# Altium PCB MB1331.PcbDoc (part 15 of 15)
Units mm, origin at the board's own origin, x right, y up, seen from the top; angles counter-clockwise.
Board outline 169.25 x 173.25 mm, 6 copper layers (Top Layer, Signal Layer 1, Signal Layer 2, Signal Layer 3, Signal Layer 4, Bottom Layer), stack 1.556 mm thick; 871 components, 699 nets, 3244 pads, 2370 vias.
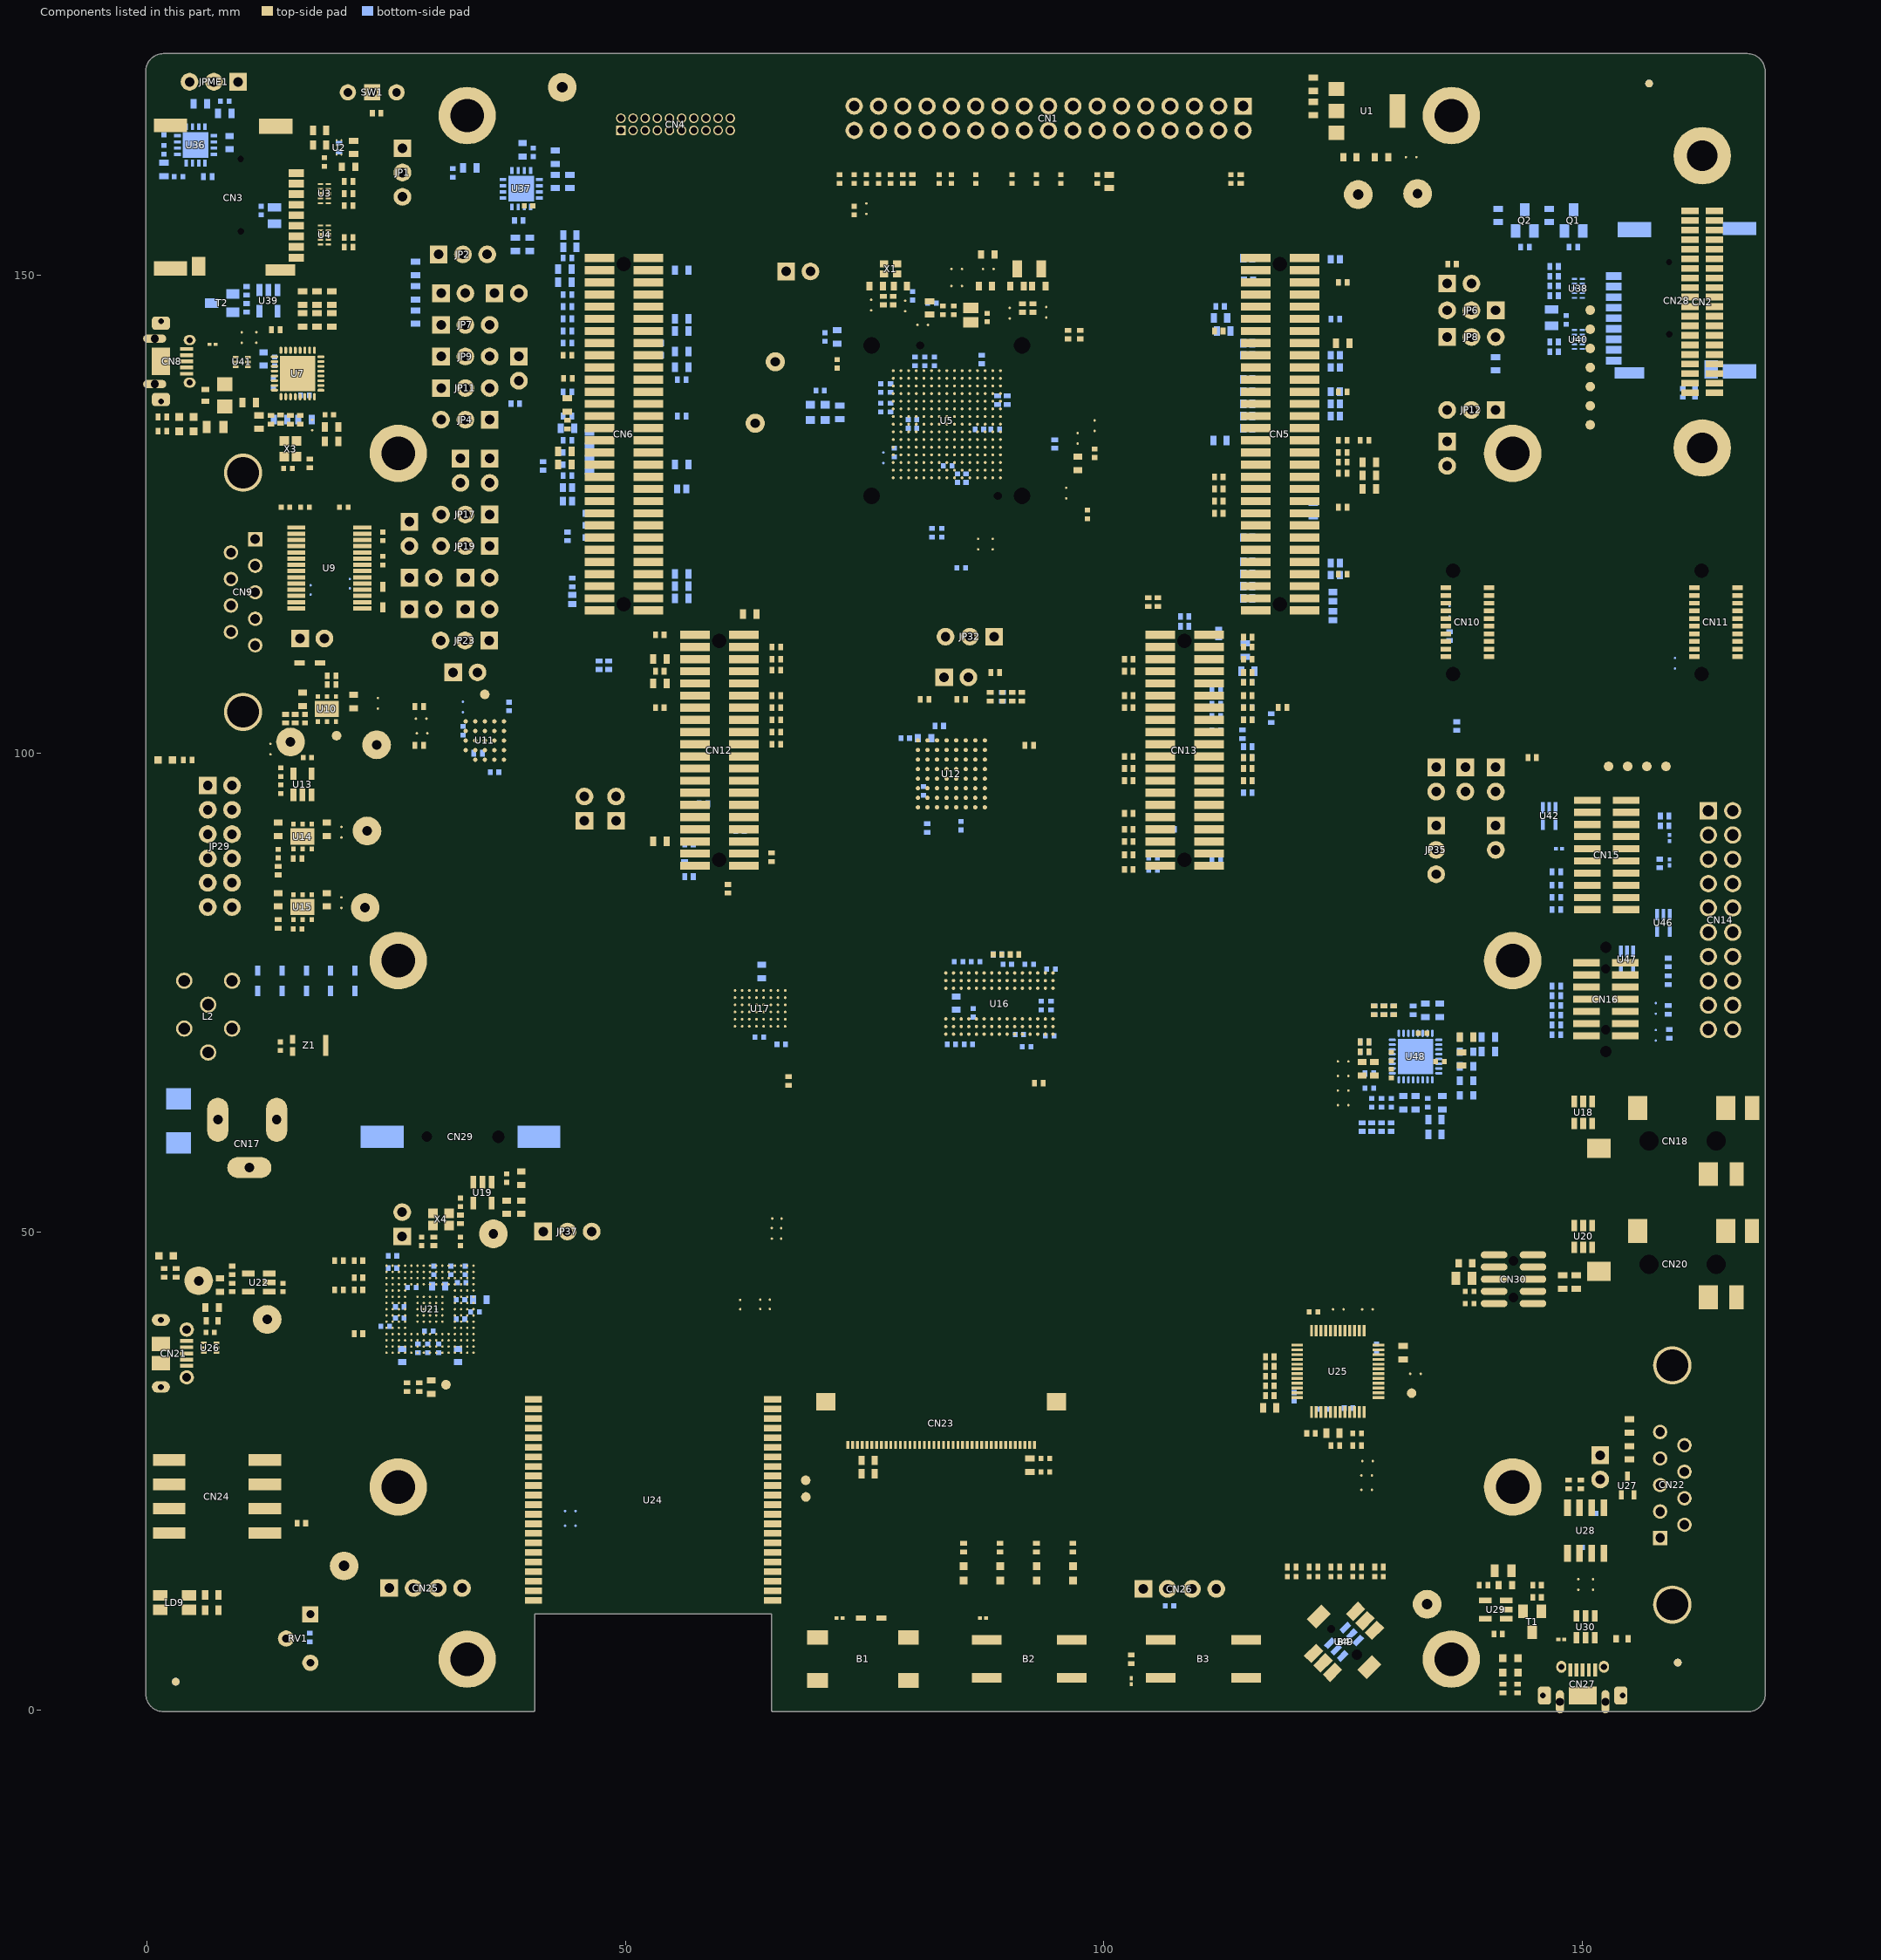
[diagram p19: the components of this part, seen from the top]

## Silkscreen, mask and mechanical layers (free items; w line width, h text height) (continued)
Drill Drawing:
  drawing of 559 lines, arcs and shapes, not listed
  text "Layer" at 186.981,220.375 h3
  text "Name" at 199.538,220.375 h3
  text "Material" at 223.825,220.375 h3
  text "Thickness" at 248.245,220.375 h3
  text "Constant" at 266.172,220.375 h3
  text "Board Layer Stack" at 282.763,220.375 h3
  text "PCB SPECIFICATIONS :" at -5.634,219.549 h3
  text "**Plating type :" at 111.416,219.199 h2.5
  text "PCB : TYPE 3" at 145.373,218.081 h3
  text "A.   MATERIAL :" at -5.634,215.549 h3
  text "FR-4" at 32.866,215.549 h3
  text "TG-170" at 49.366,215.549 h3
  text "X  TG-150" at 67.616,215.549 h3
  text "TG-140" at 83.616,215.549 h3
  text "lead Gold" at 118.141,214.724 h2.5
  text "1" at 186.981,214.375 h3
  text "Top Overlay" at 199.538,214.375 h3
  text "ASPECT-RATIO, AXE Z :" at 145.373,212.581 h3
  text "B.   MATERIAL FAMILY :" at -5.634,212.549 h3
  text "N/A" at 32.866,212.549 h3
  text "C.   SOLDERMASK COLOR :" at -5.634,209.549 h3
  text "GREEN" at 32.866,209.549 h3
  text "X  BLUE" at 49.366,209.549 h3
  text "RED" at 67.616,209.549 h3
  text "BLACK" at 83.616,209.549 h3
  text "2" at 186.981,208.375 h3
  text "Top Solder" at 199.538,208.375 h3
  text "Solder Resist" at 223.825,208.375 h3
  text "0,020mm" at 248.245,208.375 h3
  text "3,5" at 266.172,208.375 h3
  text "D.   SILKSCREEN COLOR :" at -5.634,206.549 h3
  text "X  WHITE" at 32.866,206.549 h3
  text "YELLOW" at 49.366,206.549 h3
  text "BLACK" at 67.616,206.549 h3
  text "Blue ink PANTONE 2955" at 83.616,206.549 h3
  text "6:1 to 8:1 / LEVEL \"B\"" at 145.392,205.833 h3
  text "E.   SURFACE FINISH :" at -5.634,203.549 h3
  text "X  ENIG" at 32.866,203.549 h3
  text "IMMERSION SILVER" at 49.366,203.549 h3
  text "IMMERSION TIN" at 83.616,203.549 h3
  text "3" at 186.981,202.375 h3
  text "Top Layer" at 199.538,202.375 h3
  text "Copper" at 223.825,202.375 h3
  text "0,037mm" at 248.245,202.375 h3
  text "HASL" at 32.866,200.549 h3
  text "HASL (PB-FREE)" at 49.366,200.549 h3
  text "GOLDEN FINGER" at 83.616,200.549 h3
  text "MINIMUN PARAMETERS" at 145.419,200.232 h3
  text "F.   IMPEDANCE CONTROL :" at -5.634,197.549 h3
  text "NO" at 32.866,197.549 h3
  text "X  YES  (SEE IMPEDANCE TABLE FOR DETAIL INFORMATION)" at 49.366,197.549 h3
  text "4" at 186.981,196.375 h3
  text "Dielectric 1" at 199.538,196.375 h3
  text "IT-180A 3313H" at 223.825,196.375 h3
  text "0,099mm" at 248.245,196.375 h3
  text "4,2" at 266.172,196.375 h3
  text "DEFAULT" at 145.419,194.732 h3
  text "G.   THROUGH VIA :" at -5.634,194.549 h3
  text "PLUG THE VIAS WHICH ARE COVERED WITH SOLDERMASK ONE OR TWO SIDE." at 32.866,194.549 h3
  text "PLUG MATERIAL :" at 32.866,191.549 h3
  text "X  SOLDERMASK" at 58.366,191.549 h3
  text "NON-CONDUCTIVE EPOXY." at 83.616,191.549 h3
  text "5" at 186.981,190.375 h3
  text "Signal Layer 1" at 199.538,190.375 h3
  text "Copper" at 223.825,190.375 h3
  text "0,035mm" at 248.245,190.375 h3
  text "TRACKS : 0.100mm           / GAPS : 0.100mm" at 145.419,188.982 h3
  text "H.   STACK-UP :" at -5.634,188.549 h3
  text "SEE LAYER STACK-UP SEQUENCE FOR OVERALL THICKNESS." at 32.866,188.549 h3
  text "6" at 186.981,184.375 h3
  text "Dielectric 2" at 199.538,184.375 h3
  text "IT-180A" at 223.825,184.375 h3
  text "0,130mm" at 248.245,184.375 h3
  text "4,2" at 266.172,184.375 h3
  text "7" at 186.981,178.375 h3
  text "Signal Layer 2" at 199.538,178.375 h3
  text "Copper" at 223.825,178.375 h3
  text "0,035mm" at 248.245,178.375 h3
  text "8" at 186.981,172.375 h3
  text "Dielectric 3" at 199.538,172.375 h3
  text "IT-180A 1080*2" at 223.825,172.375 h3
  text "0,885mm" at 248.245,172.375 h3
  text "4,25" at 266.172,172.375 h3
  text "9" at 186.981,166.375 h3
  text "Signal Layer 3" at 199.538,166.375 h3
  text "Copper" at 223.825,166.375 h3
  text "0,035mm" at 248.245,166.375 h3
  text "10" at 186.981,160.375 h3
  text "Dielectric 4" at 199.538,160.375 h3
  text "IT-180A" at 223.825,160.375 h3
  text "0,130mm" at 248.245,160.375 h3
  text "4,2" at 266.172,160.375 h3
  text "11" at 186.981,154.375 h3
  text "Signal Layer 4" at 199.538,154.375 h3
  text "Copper" at 223.825,154.375 h3
  text "0,035mm" at 248.245,154.375 h3
  text "12" at 186.981,148.375 h3
  text "Dielectric 5" at 199.538,148.375 h3
  text "IT-180A 3313H" at 223.825,148.375 h3
  text "0,099mm" at 248.245,148.375 h3
  text "4,2" at 266.172,148.375 h3
  text "13" at 186.981,142.375 h3
  text "Bottom Layer" at 199.538,142.375 h3
  text "Copper" at 223.825,142.375 h3
  text "0,037mm" at 248.245,142.375 h3
  text "14" at 186.981,136.375 h3
  text "Bottom Solder" at 199.538,136.375 h3
  text "Solder Resist" at 223.825,136.375 h3
  text "0,020mm" at 248.245,136.375 h3
  text "3,5" at 266.172,136.375 h3
  text "15" at 186.981,130.375 h3
  text "Bottom Overlay" at 199.538,130.375 h3
  text "Symbol" at 185.813,122.633 h2.16
  text "Count" at 194.275,122.633 h2.16
  text "Hole Size" at 203.97,122.633 h2.16
  text "Plated" at 220.415,122.633 h2.16
  text "Drill Layer Pair" at 227.843,122.633 h2.16
  text "Via/Pad" at 248.342,122.633 h2.16
  text "Pad Shape" at 257.204,122.633 h2.16
  text "Hole Length" at 268.78,122.633 h2.16
  text "Routed Path Length" at 285.225,122.633 h2.16
  text "273" at 194.275,118.905 h1.8
  text "0,20mm (7,87mil)" at 203.97,118.905 h1.8
  text "PTH" at 220.415,118.905 h1.8
  text "Top Layer - Bottom Layer" at 227.843,118.905 h1.8
  text "Via" at 248.342,118.905 h1.8
  text "Rounded" at 257.204,118.905 h1.8
  text "-" at 268.78,118.905 h1.8
  text "-" at 285.225,118.905 h1.8
  text "N" at 185.086,118.651 h1.66
  text "160" at 194.275,115.176 h1.8
  text "0,20mm (8,00mil)" at 203.97,115.176 h1.8
  text "PTH" at 220.415,115.176 h1.8
  text "Top Layer - Bottom Layer" at 227.843,115.176 h1.8
  text "Via" at 248.342,115.176 h1.8
  text "Rounded" at 257.204,115.176 h1.8
  text "-" at 268.78,115.176 h1.8
  text "-" at 285.225,115.176 h1.8
  text "K" at 185.086,114.923 h1.66
  text "150" at 194.275,111.448 h1.8
  text "0,25mm (9,84mil)" at 203.97,111.448 h1.8
  text "PTH" at 220.415,111.448 h1.8
  text "Top Layer - Bottom Layer" at 227.843,111.448 h1.8
  text "Via" at 248.342,111.448 h1.8
  text "Rounded" at 257.204,111.448 h1.8
  text "-" at 268.78,111.448 h1.8
  text "-" at 285.225,111.448 h1.8
  text "M" at 185.086,111.194 h1.66
  text "1763" at 194.275,107.72 h1.8
  text "0,25mm (10,00mil)" at 203.97,107.72 h1.8
  text "PTH" at 220.415,107.72 h1.8
  text "Top Layer - Bottom Layer" at 227.843,107.72 h1.8
  text "Via" at 248.342,107.72 h1.8
  text "Rounded" at 257.204,107.72 h1.8
  text "-" at 268.78,107.72 h1.8
  text "-" at 285.225,107.72 h1.8
  text "J" at 185.086,107.466 h1.66
  text "7" at 194.275,103.992 h1.8
  text "0,30mm (12,00mil)" at 203.97,103.992 h1.8
  text "PTH" at 220.415,103.992 h1.8
  text "Top Layer - Bottom Layer" at 227.843,103.992 h1.8
  text "Via" at 248.342,103.992 h1.8
  text "Rounded" at 257.204,103.992 h1.8
  text "-" at 268.78,103.992 h1.8
  text "-" at 285.225,103.992 h1.8
  text "L" at 185.086,103.738 h1.66
  text "17" at 194.275,100.264 h1.8
  text "0,51mm (20,00mil)" at 203.97,100.264 h1.8
  text "PTH" at 220.415,100.264 h1.8
  text "Top Layer - Bottom Layer" at 227.843,100.264 h1.8
  text "Via" at 248.342,100.264 h1.8
  text "Rounded" at 257.204,100.264 h1.8
  text "-" at 268.78,100.264 h1.8
  text "-" at 285.225,100.264 h1.8
  text "O" at 185.086,100.01 h1.66
  text "6" at 194.275,96.535 h1.8
  text "0,60mm (23,62mil)" at 203.97,96.535 h1.8
  text "PTH" at 220.415,96.535 h1.8
  text "Top Layer - Bottom Layer" at 227.843,96.535 h1.8
  text "Pad" at 248.342,96.535 h1.8
  text "(Mixed)" at 257.204,96.535 h1.8
  text "1,30mm (51,18mil)" at 268.78,96.535 h1.8
  text "0,70mm (27,56mil)" at 285.225,96.535 h1.8
  text "4" at 194.275,92.807 h1.8
  text "0,65mm (25,59mil)" at 203.97,92.807 h1.8
  text "PTH" at 220.415,92.807 h1.8
  text "Top Layer - Bottom Layer" at 227.843,92.807 h1.8
  text "Pad" at 248.342,92.807 h1.8
  text "Rounded" at 257.204,92.807 h1.8
  text "0,85mm (33,47mil)" at 268.78,92.807 h1.8
  text "0,20mm (7,88mil)" at 285.225,92.807 h1.8
  text "F" at 185.086,92.553 h1.66
  text "2" at 194.275,89.079 h1.8
  text "0,65mm (25,59mil)" at 203.97,89.079 h1.8
  text "NPTH" at 220.415,89.079 h1.8
  text "Top Layer - Bottom Layer" at 227.843,89.079 h1.8
  text "Pad" at 248.342,89.079 h1.8
  text "Rounded" at 257.204,89.079 h1.8
  text "-" at 268.78,89.079 h1.8
  text "-" at 285.225,89.079 h1.8
  text "2" at 194.275,85.351 h1.8
  text "0,70mm (27,56mil)" at 203.97,85.351 h1.8
  text "NPTH" at 220.415,85.351 h1.8
  text "Top Layer - Bottom Layer" at 227.843,85.351 h1.8
  text "Pad" at 248.342,85.351 h1.8
  text "Rounded" at 257.204,85.351 h1.8
  text "-" at 268.78,85.351 h1.8
  text "-" at 285.225,85.351 h1.8
  text "20" at 194.275,81.622 h1.8
  text "0,70mm (27,56mil)" at 203.97,81.622 h1.8
  text "PTH" at 220.415,81.622 h1.8
  text "Top Layer - Bottom Layer" at 227.843,81.622 h1.8
  text "Pad" at 248.342,81.622 h1.8
  text "Rounded" at 257.204,81.622 h1.8
  text "-" at 268.78,81.622 h1.8
  text "-" at 285.225,81.622 h1.8
  text "1" at 194.275,77.894 h1.8
  text "0,80mm (31,50mil)" at 203.97,77.894 h1.8
  text "NPTH" at 220.415,77.894 h1.8
  text "Top Layer - Bottom Layer" at 227.843,77.894 h1.8
  text "Pad" at 248.342,77.894 h1.8
  text "Rounded" at 257.204,77.894 h1.8
  text "-" at 268.78,77.894 h1.8
  text "-" at 285.225,77.894 h1.8
  text "A" at 185.086,77.641 h1.66
  text "3" at 194.275,74.166 h1.8
  text "0,80mm (31,50mil)" at 203.97,74.166 h1.8
  text "PTH" at 220.415,74.166 h1.8
  text "Top Layer - Bottom Layer" at 227.843,74.166 h1.8
  text "Pad" at 248.342,74.166 h1.8
  text "(Mixed)" at 257.204,74.166 h1.8
  text "-" at 268.78,74.166 h1.8
  text "-" at 285.225,74.166 h1.8
  text "C" at 185.086,73.912 h1.66
  text "2" at 194.275,70.438 h1.8
  text "0,85mm (33,47mil)" at 203.97,70.438 h1.8
  text "NPTH" at 220.415,70.438 h1.8
  text "Top Layer - Bottom Layer" at 227.843,70.438 h1.8
  text "Pad" at 248.342,70.438 h1.8
  text "Rounded" at 257.204,70.438 h1.8
  text "-" at 268.78,70.438 h1.8
  text "-" at 285.225,70.438 h1.8
  text "Q" at 185.086,70.184 h1.66
  text "4" at 194.275,66.71 h1.8
  text "0,85mm (33,47mil)" at 203.97,66.71 h1.8
  text "NPTH" at 220.415,66.71 h1.8
  text "Top Layer - Bottom Layer" at 227.843,66.71 h1.8
  text "Pad" at 248.342,66.71 h1.8
  text "Rounded" at 257.204,66.71 h1.8
  text "2,42mm (95,47mil)" at 268.78,66.71 h1.8
  text "1,57mm (62,01mil)" at 285.225,66.71 h1.8
  text "G" at 185.086,66.456 h1.66
  text "5" at 194.275,62.981 h1.8
  text "0,90mm (35,43mil)" at 203.97,62.981 h1.8
  text "PTH" at 220.415,62.981 h1.8
  text "Top Layer - Bottom Layer" at 227.843,62.981 h1.8
  text "Pad" at 248.342,62.981 h1.8
  text "(Mixed)" at 257.204,62.981 h1.8
  text "-" at 268.78,62.981 h1.8
  text "-" at 285.225,62.981 h1.8
  text "2" at 194.275,59.253 h1.8
  text "0,97mm (38,19mil)" at 203.97,59.253 h1.8
  text "NPTH" at 220.415,59.253 h1.8
  text "Top Layer - Bottom Layer" at 227.843,59.253 h1.8
  text "Pad" at 248.342,59.253 h1.8
  text "Rounded" at 257.204,59.253 h1.8
  text "-" at 268.78,59.253 h1.8
  text "-" at 285.225,59.253 h1.8
  text "2" at 194.275,55.525 h1.8
  text "1,00mm (39,37mil)" at 203.97,55.525 h1.8
  text "NPTH" at 220.415,55.525 h1.8
  text "Top Layer - Bottom Layer" at 227.843,55.525 h1.8
  text "Pad" at 248.342,55.525 h1.8
  text "Rounded" at 257.204,55.525 h1.8
  text "-" at 268.78,55.525 h1.8
  text "-" at 285.225,55.525 h1.8
  text "D" at 185.086,55.271 h1.66
  text "144" at 194.275,51.797 h1.8
  text "1,00mm (39,37mil)" at 203.97,51.797 h1.8
  text "PTH" at 220.415,51.797 h1.8
  text "Top Layer - Bottom Layer" at 227.843,51.797 h1.8
  text "Pad" at 248.342,51.797 h1.8
  text "Rounded" at 257.204,51.797 h1.8
  text "-" at 268.78,51.797 h1.8
  text "-" at 285.225,51.797 h1.8
  text "3" at 194.275,48.069 h1.8
  text "1,00mm (39,37mil)" at 203.97,48.069 h1.8
  text "PTH" at 220.415,48.069 h1.8
  text "Top Layer - Bottom Layer" at 227.843,48.069 h1.8
  text "Pad" at 248.342,48.069 h1.8
  text "Rounded" at 257.204,48.069 h1.8
  text "3,50mm (137,80mil)" at 268.78,48.069 h1.8
  text "2,50mm (98,43mil)" at 285.225,48.069 h1.8
  text "2" at 194.275,44.34 h1.8
  text "1,10mm (43,31mil)" at 203.97,44.34 h1.8
  text "NPTH" at 220.415,44.34 h1.8
  text "Top Layer - Bottom Layer" at 227.843,44.34 h1.8
  text "Pad" at 248.342,44.34 h1.8
  text "Rounded" at 257.204,44.34 h1.8
  text "-" at 268.78,44.34 h1.8
  text "-" at 285.225,44.34 h1.8
  text "B" at 185.086,44.087 h1.66
  text "38" at 194.275,40.612 h1.8
  text "1,10mm (43,31mil)" at 203.97,40.612 h1.8
  text "PTH" at 220.415,40.612 h1.8
  text "Top Layer - Bottom Layer" at 227.843,40.612 h1.8
  text "Pad" at 248.342,40.612 h1.8
  text "(Mixed)" at 257.204,40.612 h1.8
  text "-" at 268.78,40.612 h1.8
  text "-" at 285.225,40.612 h1.8
  text "2" at 194.275,36.884 h1.8
  text "1,19mm (46,85mil)" at 203.97,36.884 h1.8
  text "NPTH" at 220.415,36.884 h1.8
  text "Top Layer - Bottom Layer" at 227.843,36.884 h1.8
  text "Pad" at 248.342,36.884 h1.8
  text "Rounded" at 257.204,36.884 h1.8
  text "-" at 268.78,36.884 h1.8
  text "-" at 285.225,36.884 h1.8
  text "26" at 194.275,33.156 h1.8
  text "1,20mm (47,24mil)" at 203.97,33.156 h1.8
  text "PTH" at 220.415,33.156 h1.8
  text "Top Layer - Bottom Layer" at 227.843,33.156 h1.8
  text "Pad" at 248.342,33.156 h1.8
  text "(Mixed)" at 257.204,33.156 h1.8
  text "-" at 268.78,33.156 h1.8
  text "-" at 285.225,33.156 h1.8
  text "1" at 194.275,29.428 h1.8
  text "1,30mm (51,18mil)" at 203.97,29.428 h1.8
  text "NPTH" at 220.415,29.428 h1.8
  text "Top Layer - Bottom Layer" at 227.843,29.428 h1.8
  text "Pad" at 248.342,29.428 h1.8
  text "Rounded" at 257.204,29.428 h1.8
  text "-" at 268.78,29.428 h1.8
  text "-" at 285.225,29.428 h1.8
  text "I" at 185.363,29.174 h1.66
  text "12" at 194.275,25.699 h1.8
  text "1,50mm (59,06mil)" at 203.97,25.699 h1.8
  text "NPTH" at 220.415,25.699 h1.8
  text "Top Layer - Bottom Layer" at 227.843,25.699 h1.8
  text "Pad" at 248.342,25.699 h1.8
  text "Rounded" at 257.204,25.699 h1.8
  text "-" at 268.78,25.699 h1.8
  text "-" at 285.225,25.699 h1.8
  text "4" at 194.275,21.971 h1.8
  text "1,71mm (67,32mil)" at 203.97,21.971 h1.8
  text "NPTH" at 220.415,21.971 h1.8
  text "Top Layer - Bottom Layer" at 227.843,21.971 h1.8
  text "Pad" at 248.342,21.971 h1.8
  text "Rounded" at 257.204,21.971 h1.8
  text "-" at 268.78,21.971 h1.8
  text "-" at 285.225,21.971 h1.8
  text "P" at 185.086,21.717 h1.66
  text "4" at 194.275,18.243 h1.8
  text "2,00mm (78,74mil)" at 203.97,18.243 h1.8
  text "NPTH" at 220.415,18.243 h1.8
  text "Top Layer - Bottom Layer" at 227.843,18.243 h1.8
  text "Pad" at 248.342,18.243 h1.8
  text "Rounded" at 257.204,18.243 h1.8
  text "-" at 268.78,18.243 h1.8
  text "-" at 285.225,18.243 h1.8
  text "2" at 194.275,14.515 h1.8
  text "3,20mm (125,98mil)" at 203.97,14.515 h1.8
  text "PTH" at 220.415,14.515 h1.8
  text "Top Layer - Bottom Layer" at 227.843,14.515 h1.8
  text "Pad" at 248.342,14.515 h1.8
  text "Rounded" at 257.204,14.515 h1.8
  text "-" at 268.78,14.515 h1.8
  text "-" at 285.225,14.515 h1.8
  text "4" at 194.275,10.786 h1.8
  text "3,30mm (129,92mil)" at 203.97,10.786 h1.8
  text "PTH" at 220.415,10.786 h1.8
  text "Top Layer - Bottom Layer" at 227.843,10.786 h1.8
  text "Pad" at 248.342,10.786 h1.8
  text "Rounded" at 257.204,10.786 h1.8
  text "-" at 268.78,10.786 h1.8
  text "-" at 285.225,10.786 h1.8
  text "H" at 185.086,10.533 h1.66
  text "10" at 194.275,7.058 h1.8
  text "3,50mm (137,80mil)" at 203.97,7.058 h1.8
  text "PTH" at 220.415,7.058 h1.8
  text "Top Layer - Bottom Layer" at 227.843,7.058 h1.8
  text "Pad" at 248.342,7.058 h1.8
  text "Rounded" at 257.204,7.058 h1.8
  text "-" at 268.78,7.058 h1.8
  text "-" at 285.225,7.058 h1.8
  text "2675 Total" at 194.275,3.33 h1.8
  text "Slot definitions :" at 185.813,0.72 h1.8
  text "Routed Path Length" at 198.099,0.72 h1.8
  text "= Calculated from tool start centre position to tool end centre position." at 213.319,0.72 h1.8
  text "Hole Length" at 198.099,-0.771 h1.8
  text "= Routed Path Length + Tool Size = Slot length as defined in the PCB layout" at 207.668,-0.771 h1.8

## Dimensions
0,171.25 to 169,171.275 on M2-Board Dimensions
131.25,126.6 to 168.75,126.6 on M3-Top Dimensions
131.25,126.6 to 131.25,100.6 on M3-Top Dimensions
1.725,173 to 1.725,0 on M2-Board Dimensions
